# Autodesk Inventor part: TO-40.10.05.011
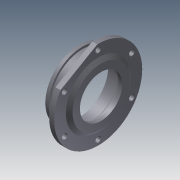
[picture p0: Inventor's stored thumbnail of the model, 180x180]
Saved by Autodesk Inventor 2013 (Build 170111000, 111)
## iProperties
Shininess: 25.0
Angle Display Precision: 2
Document Length Units: 11269
Document Angle Units: 11279
Document Time Units: 11290
Document Mass Units: 11283
Document Length Units Precision: 3
Document Angle Units Precision: 2
Created: 2002-05
Part Number: TO-40.10.05.011
Document SubType Name: Modeling
Designer: SaAlex
Density: 1 g/cm^3
Material: Generic
Mass: 473.159 g
Surface Area: 1047.81 cm^2
Volume: 473.159 cm^3
Density: 0.0
Volumn: 0.0
Area: 0.0
PropertySet Name: Model Information
Control State: 0
Master: False
Checked Out: True
Last Check In Date: 2008-10-15
Checked Out Date: 2008-10-15
Author: SaAlex
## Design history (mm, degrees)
sketch "Sketch1"
  geometry: L1 (17.5, 62.5)-(17.5, 50.5); L2 (4.5, 62.5)-(17.5, 62.5); L3 (4.5, 62.5)-(2.5, 63.655); L4 (2.5, 70)-(2.5, 63.655); L5 (-26.5, 70)-(2.5, 70); L6 (-26.5, 80)-(-26.5, 70); L7 (-26.5, 80)-(-18.5, 80); L8 (-18.5, 80)-(-18.5, 75); L9 (-18.5, 75)-(-11.5, 75); L10 (-11.5, 80)-(-11.5, 75); L11 (-11.5, 80)-(7.5, 80); L12 (7.5, 105)-(7.5, 80); L13 (7.5, 105)-(19.5, 105); L14 (19.5, 105)-(19.5, 77); L15 (19.5, 77)-(26.5, 68); L16 (26.5, 68)-(26.5, 50.5); L17 (17.5, 50.5)-(26.5, 50.5); L18 (-23.5, 0)-(26.5, 0); L19 (-23.5, 0)-(26.5, 0)
  constraints: 38 end point, 8 horizontal, 8 vertical, 1 collinear, 1 other
  dimensions: "d1" = 53 horizontal distance of L5.start L16.end; "d3" = 12 distance of L12.start L13.end; "d5" = 34 distance of L11.end L6.start; "d7" = 8 distance of L6.start L7.end; "d9" = 7 distance of L8.end L9.end; "d11" = 50.5 distance of L16.end L18.end; "d13" = 68 distance of L15.end L18.end; "d15" = 77 vertical distance of L14.end L18.end; "d17" = 62.5 vertical distance of L1.start L18.end; "d19" = 70 vertical distance of L5.start L18.start; "d21" = 29 distance of L5.start L4.start; "d23" = 15 horizontal distance of L4.start L1.end; "d25" = 80 vertical distance of L6.start L18.start; "d27" = 75 vertical distance of L9.end L18.start; "d29" = 2 horizontal distance of L2.start L3.end; "d31" = 30 deg angle of L2 L3; "d33" = 105 vertical distance of L12.start L18.start
revolve "RevolutionFull1" sketch "Sketch1" stored, may be unused: angle "d34" = 360 deg
node "WorkAxis1"
sketch "Sketch2"
  geometry: C1 r 6.5 at (-92.5, 0); C2 r 50.5 at (0, 0) reference
  constraints: 1 centre point
  dimensions: "d38" = 13 diameter of C1; "d40" = 92.5 distance of C1.centre C2.centre
extrude "ExtrusionThru1" cut sketch "Sketch2" stored distance "d42" = 0.13; taper "d43" = 0 deg
pattern_circular "PolarArray1" dims angle "d46" = 360 deg
sketch "Sketch3"
  geometry: C1 r 15 at (-50, -29); C2 r 50.5 at (0, 0) reference
  constraints: 1 centre point
  dimensions: "d48" = 30 diameter of C1; "d50" = 29 vertical distance of C1.centre C2.centre; "d52" = 50 horizontal distance of C1.centre C2.centre
extrude "ExtrusionBlind1" cut sketch "Sketch3" distance "d53" = 31; taper "d54" = 0 deg
sketch "Sketch4"
  geometry: L1 (116.675, 18.088)-(34.007, -125.098); L2 (135.468, 234.638)-(0, 0); L3 (0, -241.183)-(0, 0); C1 r 105 at (0, 0) reference; C2 r 50.5 at (0, 0) reference; A1 r 105 centre (19.277, -21.136) between (34.007, -125.098) and (116.675, 18.088)
  constraints: 6 end point, 2 point on circle, 1 centre point, 1 parallel, 1 vertical
  dimensions: "d56" = 105 radius of A1; "d58" = 30 deg angle of L3 L2; "d60" = 92 distance between parallel lines of L2 L1; "d62" = 165.336 distance of L1.start L1.end
extrude "ExtrusionThru2" cut sketch "Sketch4" stored distance "d63" = 0.13; taper "d64" = 0 deg
body "Solid1"
other parameters: "d0" = 53 (derived), "d2" = 12 (derived), "d4" = 34 (derived), "d6" = 8 (derived), "d8" = 7 (derived), "d10" = 50.5 (derived), "d12" = 68 (derived), "d14" = 77 (derived), "d16" = 62.5 (derived), "d20" = 29 (derived), "d22" = 15 (derived), "d26" = 75 (derived), "d28" = 2 (derived), "d30" = 30 deg (derived), "d32" = 105 (derived), "d35" = 0, "d36" = 0, "d37" = 13 (derived), "d39" = 92.5 (derived), "d41" = 0 (derived), "d49" = 29 (derived), "d55" = 105 (derived), "d57" = 30 deg (derived), "d59" = 92 (derived), "d61" = 165.336 (derived)
